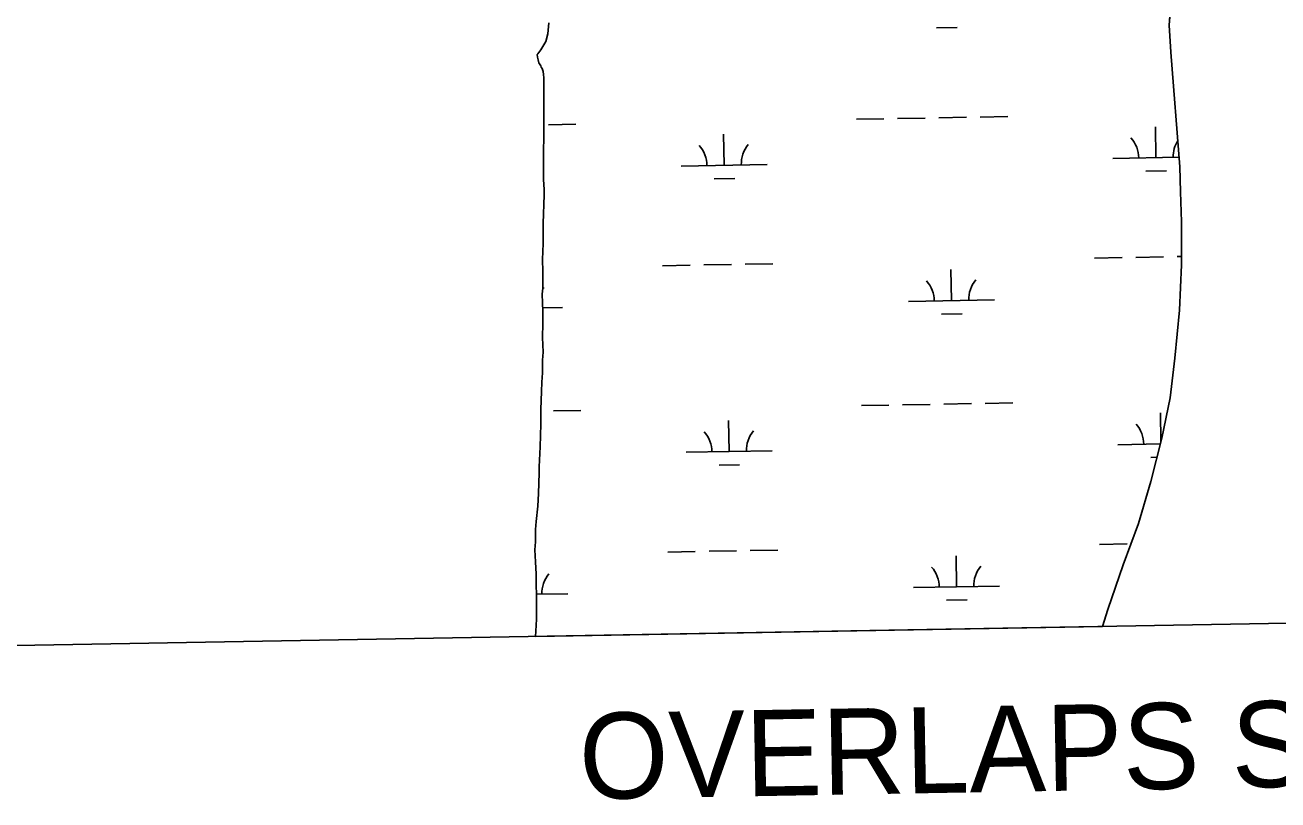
# Model space of a CAD drawing. Extents: x 3903937 to 3942190, y 260677 to 286651.
# Drawn here: x 3914446 to 3915902, y 265947 to 266847 of the extents above; entities that cross this region are included whole.
import ezdxf

# ---------------------------------------------------------------- set-up
doc = ezdxf.new("R2010")
doc.units = 0
for name, color, linetype in [('V-ANNO-TEXT', 7, 'Continuous'), ('V-GRID-FRAM', 7, 'Continuous'), ('V-TOPO-SHOR', 7, 'Continuous'), ('V-WETL-SWMP', 7, 'Continuous')]:
    doc.layers.add(name, color=color, linetype=linetype)

msp = doc.modelspace()

# ---------------------------------------------------------------- linework, layer by layer
at = {"layer": 'V-GRID-FRAM'}
msp.add_lwpolyline([(3907892.2, 284196.1), (3939773.2, 284757.2), (3940101.1, 266577.6), (3908204.3, 266016.2), (3907892.2, 284196.1)], dxfattribs=at)
at = {"layer": 'V-TOPO-SHOR'}
for points in [[(3915777.2, 266815.4), (3915775.4, 266846.7), (3915780.1, 266909.9)], [(3915703.9, 266167.7), (3915721.7, 266219.8), (3915739.5, 266267.7), (3915754, 266316.5), (3915766.6, 266366.8), (3915776.4, 266413.8), (3915781.8, 266459.8), (3915787.3, 266515.8), (3915789.5, 266568.1), (3915789.8, 266618.4), (3915788.5, 266653.1), (3915787.7, 266682.1), (3915777.2, 266815.4)], [(3915697.8, 266148.1), (3915703.9, 266167.7)]]:
    msp.add_lwpolyline(points, dxfattribs=at)
at = {"layer": 'V-WETL-SWMP'}
for p, q in [((3915780.1, 266909.9), (3915775.4, 266846.7)), ((3915053.3, 266836.8), (3915054.4, 266849.5)), ((3915504.8, 266843.7), (3915528.8, 266844.1)), ((3915775.4, 266846.7), (3915777.2, 266815.4)), ((3915045.3, 266818.2), (3915050.9, 266827.7)), ((3915050.9, 266827.7), (3915053.3, 266836.8)), ((3915040.9, 266812.7), (3915041.5, 266813.5)), ((3915041.3, 266809.7), (3915040.9, 266812.7)), ((3915041.5, 266813.5), (3915045.3, 266818.2)), ((3915777.2, 266815.4), (3915787.7, 266682.1)), ((3915041.9, 266806.6), (3915041.3, 266809.7)), ((3915042.4, 266804.4), (3915041.9, 266806.6)), ((3915043, 266802.8), (3915042.4, 266804.4)), ((3915044.4, 266800.5), (3915043, 266802.8)), ((3915045, 266799.4), (3915044.4, 266800.5)), ((3915045.7, 266798.1), (3915045, 266799.4)), ((3915046.6, 266796.3), (3915045.7, 266798.1)), ((3915047.9, 266792.9), (3915046.6, 266796.3)), ((3915048.1, 266789.3), (3915047.9, 266792.9)), ((3915048.8, 266785.5), (3915048.1, 266789.3)), ((3915048.8, 266780.8), (3915048.8, 266785.5)), ((3915048.7, 266777.7), (3915048.8, 266780.8)), ((3915048.7, 266759.9), (3915048.7, 266777.7)), ((3915048.6, 266755.3), (3915048.7, 266759.9)), ((3915048.6, 266749.8), (3915048.6, 266755.3)), ((3915048.5, 266738.2), (3915048.6, 266743.6)), ((3915048.5, 266734.3), (3915048.5, 266738.2)), ((3915048.6, 266743.6), (3915048.6, 266749.8)), ((3915459.8, 266738.3), (3915491.8, 266738.8)), ((3915507.8, 266739.1), (3915539.8, 266739.7)), ((3915555.8, 266740), (3915587.8, 266740.5)), ((3915048.5, 266728.9), (3915048.5, 266734.3)), ((3915048.5, 266723.5), (3915048.5, 266728.9)), ((3915053.9, 266731.1), (3915085.9, 266731.7)), ((3915411.8, 266737.4), (3915443.8, 266738)), ((3915759.9, 266692.8), (3915759.3, 266728.8)), ((3915048.3, 266693.2), (3915048.5, 266723.5)), ((3915258.1, 266684), (3915257.5, 266720)), ((3915048.2, 266677.7), (3915048.3, 266693.2)), ((3915208.1, 266683.1), (3915308.1, 266684.8)), ((3915710, 266691.9), (3915786.8, 266693.3)), ((3915787.7, 266682.1), (3915788.5, 266653.1)), ((3915048.2, 266667.6), (3915048.2, 266677.7)), ((3915048.9, 266656), (3915048.2, 266667.6)), ((3915246.4, 266668.3), (3915270.4, 266668.7)), ((3915748.2, 266677.2), (3915772.2, 266677.6)), ((3915048.9, 266649.8), (3915048.9, 266656)), ((3915788.5, 266653.1), (3915789.8, 266618.4)), ((3915047.9, 266616.5), (3915048.9, 266649.8)), ((3915047.8, 266593.2), (3915047.9, 266607.9)), ((3915047.9, 266607.9), (3915047.9, 266616.5)), ((3915789.8, 266618.4), (3915789.5, 266568.1)), ((3915046.9, 266574.6), (3915047.8, 266593.2)), ((3915047.6, 266560.6), (3915046.9, 266574.6)), ((3915186.7, 266567.3), (3915218.7, 266567.8)), ((3915234.7, 266568.1), (3915266.7, 266568.7)), ((3915282.7, 266568.9), (3915314.7, 266569.5)), ((3915688.6, 266576.1), (3915720.6, 266576.7)), ((3915736.6, 266576.9), (3915768.6, 266577.5)), ((3915784.6, 266577.8), (3915789.6, 266577.9)), ((3915789.5, 266568.1), (3915787.3, 266515.8)), ((3915047.5, 266541.3), (3915047.6, 266560.6)), ((3915522.4, 266526.7), (3915521.7, 266562.7)), ((3915046.7, 266534.3), (3915047.5, 266541.3)), ((3915047.4, 266514.1), (3915046.7, 266534.3)), ((3915472.4, 266525.8), (3915572.4, 266527.6)), ((3915047.3, 266518.4), (3915070.5, 266518.8)), ((3915047.3, 266500.2), (3915047.4, 266514.1)), ((3915510.6, 266511.1), (3915534.6, 266511.5)), ((3915787.3, 266515.8), (3915781.8, 266459.8)), ((3915047.2, 266483.9), (3915047.3, 266500.2)), ((3915047.9, 266466.8), (3915047.2, 266483.9)), ((3915047.1, 266457.5), (3915047.9, 266466.8)), ((3915047, 266442.8), (3915047.1, 266447.4)), ((3915047.1, 266447.4), (3915047.1, 266457.5)), ((3915781.8, 266459.8), (3915776.4, 266413.8)), ((3915046.2, 266431.9), (3915047, 266442.8)), ((3915045.3, 266400.1), (3915046.1, 266421.1)), ((3915046.1, 266421.1), (3915046.2, 266431.9)), ((3915417.6, 266404.8), (3915449.6, 266405.4)), ((3915465.6, 266405.6), (3915497.6, 266406.2)), ((3915513.6, 266406.5), (3915545.6, 266407)), ((3915561.6, 266407.3), (3915593.6, 266407.9)), ((3915776.4, 266413.8), (3915766.6, 266366.8)), ((3915045.2, 266383.1), (3915045.3, 266400.1)), ((3915059.8, 266398.5), (3915091.8, 266399.1)), ((3915765.7, 266363.3), (3915765.2, 266396.2)), ((3915044.3, 266356.7), (3915045.2, 266383.1)), ((3915264, 266351.3), (3915263.3, 266387.3)), ((3915715.8, 266359.3), (3915765, 266360.2)), ((3915766.6, 266366.8), (3915754, 266316.5)), ((3915043.4, 266333.5), (3915044.3, 266356.7)), ((3915214, 266350.5), (3915314, 266352.2)), ((3915043.3, 266326.5), (3915043.4, 266333.5)), ((3915252.2, 266335.7), (3915276.2, 266336.1)), ((3915754.1, 266344.5), (3915761.1, 266344.7)), ((3915042.4, 266302.5), (3915043.3, 266326.5)), ((3915754, 266316.5), (3915739.5, 266267.7)), ((3915041.6, 266287.7), (3915042.4, 266302.5)), ((3915039.9, 266269.9), (3915041.6, 266287.7)), ((3915039, 266246.6), (3915039.1, 266260.6)), ((3915039.1, 266260.6), (3915039.9, 266269.9)), ((3915739.5, 266267.7), (3915721.7, 266219.8)), ((3915038.2, 266237.3), (3915039, 266246.6)), ((3915694.4, 266243.5), (3915726.4, 266244)), ((3915038.9, 266223.4), (3915038.2, 266237.3)), ((3915192.6, 266234.6), (3915224.6, 266235.2)), ((3915240.6, 266235.5), (3915272.6, 266236)), ((3915288.6, 266236.3), (3915320.6, 266236.9)), ((3915528.2, 266194.1), (3915527.6, 266230.1)), ((3915039.6, 266208.7), (3915038.9, 266223.4)), ((3915721.7, 266219.8), (3915703.9, 266167.7)), ((3915039.6, 266197.8), (3915039.6, 266208.7)), ((3915040.3, 266183.8), (3915039.6, 266197.8)), ((3915040.2, 266185.5), (3915076.4, 266186.2)), ((3915478.2, 266193.2), (3915578.2, 266195)), ((3915040.2, 266176.1), (3915040.3, 266183.8)), ((3915040.2, 266163.7), (3915040.2, 266176.1)), ((3915516.5, 266178.5), (3915540.5, 266178.9)), ((3915039.3, 266142.7), (3915040.1, 266156.7)), ((3915040.1, 266156.7), (3915040.2, 266163.7)), ((3915703.9, 266167.7), (3915697.8, 266148.1)), ((3915697.8, 266148.1), (3915038.8, 266136.5)), ((3915038.8, 266136.5), (3915039.3, 266142.7))]:
    msp.add_line(p, q, dxfattribs=at)
for centre, start, end in [((3915704.7, 266692.3), 0.2366, 41.7802), ((3915815.2, 266694.2), 148.0181, 181.7802), ((3915202.9, 266683.5), 0.2366, 41.7802), ((3915313.3, 266685.4), 140.2366, 181.7802), ((3915467.1, 266526.2), 0.2366, 41.7802), ((3915577.6, 266528.2), 140.2366, 181.7802), ((3915075.8, 266519.3), 140.2366, 143.4924), ((3915208.7, 266350.8), 0.2366, 41.7802), ((3915319.2, 266352.8), 140.2366, 181.7802), ((3915710.6, 266359.7), 0.2366, 41.7802), ((3915473, 266193.6), 0.2366, 41.7802), ((3915583.4, 266195.6), 140.2366, 181.7802), ((3915081.6, 266186.7), 140.2366, 181.7802)]:
    msp.add_arc(centre, 35.2, start, end, dxfattribs=at)

# ---------------------------------------------------------------- texts
at = {"layer": 'V-ANNO-TEXT'}
msp.add_text('OVERLAPS SHEET 115', height=100, rotation=1.0084, dxfattribs=at).set_placement((3915090.4, 265947.3))

doc.saveas('drawing.dxf')
